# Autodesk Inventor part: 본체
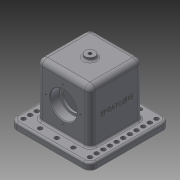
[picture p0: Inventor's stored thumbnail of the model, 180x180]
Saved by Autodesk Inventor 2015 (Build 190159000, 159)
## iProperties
Created: 2018-11
Part Number: 본체
Material: 일반
Document SubType Name: Modeling
Designer: now
Density: 1 g/cm^3
Appearance: 기본값
Mass: 376.063 g
Surface Area: 780.986 cm^2
Volume: 376.063 cm^3
Author: now
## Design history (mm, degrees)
sketch "스케치1"
  geometry: L1 (-60, -60)-(60, -60); L2 (60, -60)-(60, 60); L3 (60, 60)-(-60, 60); L4 (-60, 60)-(-60, -60); L5 (-60, -60)-(60, 60); L6 (60, -60)-(-60, 60); 1 further point
  constraints: 12 end point, 2 midpoint, 2 parallel, 1 horizontal, 1 perpendicular
  dimensions: "d0" = 120 distance of L3.end L1.start; "d1" = 120 distance of L2.end L3.end
extrude "돌출1" new body sketch "스케치1" distance "d2" = 10; taper "d3" = 0 deg
sketch "스케치2"
  geometry: L1 (-40, -40)-(40, -40); L2 (40, -40)-(40, 40); L3 (40, 40)-(-40, 40); L4 (-40, 40)-(-40, -40); L5 (-40, -40)-(40, 40); L6 (40, -40)-(-40, 40); 1 further point
  constraints: 12 end point, 2 midpoint, 2 parallel, 1 horizontal, 1 perpendicular
  dimensions: "d4" = 80 distance of L3.end L1.start; "d5" = 80 distance of L2.end L3.end
extrude "돌출2" join sketch "스케치2" distance "d6" = 80; taper "d7" = 0 deg
fillet "모깎기1" dims "d13" = 10
sketch "스케치6"
  geometry: A1 r 10 centre (-50, -50) between (-60, -50) and (-50, -60) reference; 1 further point
hole "구멍1" sketch "스케치6" at (-50, -50) diameter "d14" = 6.6; stored, may be unused: countersink angle "d18" = 90 deg, drill point angle "d20" = 118 deg; dims "d15" = 6, "d16" = 4, "d17" = 2, "d19" = 8
fillet "모깎기2" dims "d53" = 8
fillet "모깎기3" dims "d60" = 8
fillet "모깎기4" dims "d61" = 8
fillet "모깎기5" dims "d62" = 3
sketch "스케치18"
  geometry: L1 (30, -23)-(-30, -23); L2 (-30, -23)-(-30, 23); L3 (-30, 23)-(30, 23); L4 (30, 23)-(30, -23); L5 (30, -23)-(-30, 23); L6 (-30, -23)-(30, 23); 1 further point
  constraints: 12 end point, 2 midpoint, 2 parallel, 1 horizontal, 1 perpendicular
  dimensions: "d75" = 60 distance of L1.start L1.end; "d76" = 46 distance of L1.end L2.end
extrude "돌출9" cut sketch "스케치18" distance "d77" = 80; taper "d78" = 0 deg
sketch "스케치26"
  geometry: C1 r 16.5 at (32, 38); 1 further point
  constraints: 1 centre point, 1 vertical alignment
  dimensions: "d104" = 48 distance of point (32, -10) C1.centre; "d105" = 33 diameter of C1
extrude "돌출14" cut sketch "스케치26" stored distance "d106" = 3; taper "d107" = 0 deg
sketch "스케치28"
  geometry: C1 r 16.5 at (32, 38) reference; C2 r 20 at (32, 38); 1 further point
  constraints: 1 centre point, 1 coincident
  dimensions: "d108" = 40 diameter of C2
extrude "돌출15" cut sketch "스케치28" distance "d109" = 14; taper "d110" = 0 deg
chamfer "모따기3" distance "d111" = 1; stored, may be unused: second distance "d112" = 2, angle "d113" = 45 deg
sketch "스케치29"
  geometry: C1 r 7.5 at (0, 0); 1 further point
  constraints: 1 centre point, 1 coincident
  dimensions: "d114" = 15 diameter of C1
extrude "돌출16" join sketch "스케치29" distance "d115" = 5; taper "d116" = 0 deg
sketch "스케치30"
  geometry: C1 r 7.5 at (0, 0) reference
hole "구멍5" sketch "스케치30" at (0, 0) diameter "d117" = 4.917; stored, may be unused: countersink angle "d121" = 90 deg, drill point angle "d123" = 118 deg; dims "d118" = 12, "d119" = 4, "d120" = 2, "d122" = 17.1
fillet "모깎기7" dims "d124" = 3
fillet "모깎기8" dims "d125" = 0.6
fillet "모깎기9" dims "d126" = 0.6
sketch "스케치31"
  geometry: C1 r 21 at (32, -38) reference; 2 further points
  constraints: 1 vertical alignment
  dimensions: "d127" = 26 distance of point (32, -64) C1.centre
hole "구멍6" sketch "스케치31" at (32, -64) diameter "d128" = 3.242; stored, may be unused: countersink angle "d132" = 90 deg, drill point angle "d134" = 118 deg; dims "d129" = 8, "d130" = 4, "d131" = 2, "d133" = 10
sketch "스케치32"
  geometry: L1 (10, -18)-(10, 82) reference; 3 further points
  constraints: 1 horizontal alignment, 1 midpoint, 1 other
  dimensions: "d138" = 48 distance from line of L1 point (-38, 32)
fillet "모깎기10" dims "d139" = 3
fillet "모깎기11" dims "d140" = 3
fillet "모깎기12" dims "d141" = 3
feature "엠보싱1" dims "d142" = 0.5, "d143" = 0
fillet "모깎기13" dims "d144" = 3
node "솔리드1"
pattern_linear "직사각형 패턴4" dims "d56" = 25
pattern_linear "직사각형 패턴5" dims "d59" = 10
mirror "대칭3"
mirror "대칭4"
mirror "대칭5"
pattern_circular "원형 패턴1" dims angle "d136" = 360 deg
mirror "대칭6"
